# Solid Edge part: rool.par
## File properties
Author: Romil
Template: iso part.par
Last saved by: Romil
Revision: 40
Application: Solid Edge
Accuracy: 0.990
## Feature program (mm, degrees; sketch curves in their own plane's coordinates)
sketch for "unnamed Protrusion 1" plane through (0, 0, 0) normal (1, 0, 0) x-axis (0, 1, 0)
  circle centre (0, 0) radius 11.9
extrude "unnamed Protrusion 1" add finite 3.8 symmetric
sketch for "unnamed Cutout 1" plane through (0, 0, 0) normal (1, 0, 0) x-axis (0, 1, 0)
  arc centre (0, 0) radius 2.55 from (-0.9006, 2.3857) to (1.6939, 1.9061) cw
  line (1.0607, 1.2728) -> (1.6939, 1.9061)
  arc centre (1.1667, 1.1667) radius 0.15 from (1.2728, 1.0607) to (1.0607, 1.2728) cw
  line (1.9061, 1.6939) -> (1.2728, 1.0607)
  arc centre (0, 0) radius 2.55 from (1.9061, 1.6939) to (2.3857, -0.9006) cw
  line (1.8031, -0.9006) -> (2.3857, -0.9006)
  arc centre (1.8031, -1.8031) radius 0.9025 from (0.9006, -1.8031) to (1.8031, -0.9006) cw
  line (0.9006, -2.3857) -> (0.9006, -1.8031)
  arc centre (0, 0) radius 2.55 from (0.9006, -2.3857) to (-1.6939, -1.9061) cw
  line (-1.0607, -1.2728) -> (-1.6939, -1.9061)
  arc centre (-1.1667, -1.1667) radius 0.15 from (-1.2728, -1.0607) to (-1.0607, -1.2728) cw
  line (-1.9061, -1.6939) -> (-1.2728, -1.0607)
  arc centre (0, 0) radius 2.55 from (-1.9061, -1.6939) to (-2.3857, 0.9006) cw
  line (-1.8031, 0.9006) -> (-2.3857, 0.9006)
  arc centre (-1.8031, 1.8031) radius 0.9025 from (-0.9006, 1.8031) to (-1.8031, 0.9006) cw
  line (-0.9006, 2.3857) -> (-0.9006, 1.8031)
extrude "unnamed Cutout 1" cut finite 136.9727 symmetric
sketch for "unnamed Cutout 2" plane through (0, 0, 0) normal (1, 0, 0) x-axis (0, 1, 0)
  circle centre (-8, 0) radius 2.4
extrude "unnamed Cutout 2" cut finite 82.9182 symmetric
sketch for "ExtrudedCutout_44" plane through (-1.9, 0, 0) normal (-1, 0, 0) x-axis (0, -1, 0)
  circle centre (8, 0) radius 3.1
extrude "ExtrudedCutout_44" cut finite 0.9 along -normal
pattern "unnamed Pattern 1" of "unnamed Cutout 2", "ExtrudedCutout_44"
extrude "unnamed Cutout 3" cut finite 82.9182 symmetric
extrude "unnamed Cutout 4" cut finite 0.9
extrude "unnamed Cutout 5" cut finite 82.9182 symmetric
extrude "unnamed Cutout 6" cut finite 0.9
extrude "unnamed Cutout 7" cut finite 82.9182 symmetric
extrude "unnamed Cutout 8" cut finite 0.9
extrude "unnamed Cutout 9" cut finite 82.9182 symmetric
extrude "unnamed Cutout 10" cut finite 0.9
extrude "unnamed Cutout 11" cut finite 82.9182 symmetric
extrude "unnamed Cutout 12" cut finite 0.9
mirror "unnamed Mirror 1" of "ExtrudedCutout_44", "unnamed Pattern 1" about plane through (0, 0, 0) normal (1, 0, 0)
extrude "unnamed Cutout 13" cut finite 0.9
extrude "unnamed Cutout 14" cut finite 82.9182 symmetric
extrude "unnamed Cutout 15" cut finite 0.9
extrude "unnamed Cutout 16" cut finite 82.9182 symmetric
extrude "unnamed Cutout 17" cut finite 0.9
extrude "unnamed Cutout 18" cut finite 82.9182 symmetric
extrude "unnamed Cutout 19" cut finite 0.9
extrude "unnamed Cutout 20" cut finite 82.9182 symmetric
extrude "unnamed Cutout 21" cut finite 0.9
extrude "unnamed Cutout 22" cut finite 82.9182 symmetric
extrude "unnamed Cutout 23" cut finite 0.9
sketch for "unnamed RevolvedCutout 1" plane through (0, 0, 0) normal (0, -1, 0) x-axis (1, 0, 0)
  line (-1.9, 12.9479) -> (1.9, 12.9479)
  line (1.9, 12.9479) -> (1.9, 11.9)
  line (1.9, 11.9) -> (0.835, 11.9)
  arc centre (0.835, 11.7) radius 0.2 from (0.635, 11.7) to (0.835, 11.9) cw
  line (0.635, 11.35) -> (0.635, 11.7)
  arc centre (0.335, 11.35) radius 0.3 from (0.335, 11.05) to (0.635, 11.35) ccw
  line (0.335, 11.05) -> (-0.335, 11.05)
  arc centre (-0.335, 11.35) radius 0.3 from (-0.335, 11.05) to (-0.635, 11.35) cw
  line (-0.635, 11.35) -> (-0.635, 11.7)
  arc centre (-0.835, 11.7) radius 0.2 from (-0.835, 11.9) to (-0.635, 11.7) cw
  line (-0.835, 11.9) -> (-1.9, 11.9)
  line (-1.9, 11.9) -> (-1.9, 12.9479)
revolve "unnamed RevolvedCutout 1" cut finite 360 deg
sketch for "unnamed RevolvedCutout 2" plane through (0, 0, 0) normal (0, -1, 0) x-axis (1, 0, 0)
  line (-6.9503, 0) -> (-6.9503, 8)
  line (-6.9503, 8) -> (-6.9503, 9.55)
  line (-7.0128, 10.2946) -> (-6.9503, 9.55)
  line (-1.9, 10.2946) -> (-7.0128, 10.2946)
  line (-1.9, 9.653) -> (-1.9, 10.2946)
  arc centre (-1.6, 9.653) radius 0.3 from (-1.8368, 9.4687) to (-1.9, 9.653) cw
  line (-1.8368, 9.4687) -> (-1.0632, 8.4744)
  arc centre (-1.3, 8.2902) radius 0.3 from (-1, 8.2902) to (-1.0632, 8.4744) ccw
  line (-1, 3.6) -> (-1, 8.2902)
  line (-1.9, 3.6) -> (-1, 3.6)
  line (-1.9, 0) -> (-1.9, 3.6)
  line (-4.2059, 0) -> (-1.9, 0)
  line (-4.2059, 0) -> (-6.9503, 0)
revolve "unnamed RevolvedCutout 2" cut finite 360 deg
mirror "unnamed Mirror 2" of "unnamed RevolvedCutout 2" about plane through (0, 0, 0) normal (1, 0, 0)
revolve "unnamed RevolvedCutout 3" cut finite 360 deg
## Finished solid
Body 1: solid body, 87 faces, 218 edges, 128 vertices.
  Faces by surface: cylinder 31, torus 28, plane 16, cone 12
  Edges by curve: circle 114, intersection 72, line 32
Bounding box of the edges (mm; curved faces can reach further): 3.800 x 23.800 x 23.800, from (-1.9, -11.9, -11.9) to (1.9, 11.9, 11.9).
Cylindrical faces by radius (mm): R0.15 x2, R0.9025 x2, R2.4 x6, R2.55 x4, R3.1 x12, R3.6 x2, R11.05 x1, R11.9 x2
Conical faces (half-angle, radius in mm at the cone's reference point): 52.1184 deg R8.4744 x6, 52.1184 deg R9.4687 x6
Toroidal faces (ring radius, tube radius in mm): R8.2902 r0.3 x12, R9.653 r0.3 x12, R11.35 r0.3 x2, R11.7 r0.2 x2
Planar faces by outward normal: +x 4, +y 1, +z 1, -x 4, -y 1, -z 1, oblique 4
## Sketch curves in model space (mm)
line (-1.9, 0, 0) -> (-1.9, 0, 3.6)
line (-1.9, 0, 3.6) -> (-1, 0, 3.6)
line (-1, 0, 3.6) -> (-1, 0, 8.2902)
arc centre (-1.3, 0, 8.2902) radius 0.3 from (-1, 0, 8.2902) through (-1.0162, 0, 8.3876) to (-1.0632, 0, 8.4744)
line (-1.8368, 0, 9.4687) -> (-1.0632, 0, 8.4744)
arc centre (-1.6, 0, 9.653) radius 0.3 from (-1.8368, 0, 9.4687) through (-1.8838, 0, 9.5556) to (-1.9, 0, 9.653)
line (-1.9, 0, 9.653) -> (-1.9, 0, 10.2946)
line (-1.9, 0, 10.2946) -> (-7.0128, 0, 10.2946)
line (-7.0128, 0, 10.2946) -> (-6.9503, 0, 9.55)
line (-6.9503, 0, 8) -> (-6.9503, 0, 9.55)
line (-6.9503, 0, 0) -> (-6.9503, 0, 8)
line (-4.2059, 0, 0) -> (-6.9503, 0, 0)
line (-4.2059, 0, 0) -> (-1.9, 0, 0)
circle centre (-1.9, -8, 0) radius 3.1
line (-2.4774, 0, 0) -> (5.0483, 0, 0)
arc centre (-0.335, 0, 3.05) radius 0.3 from (-0.335, 0, 2.75) through (-0.5532, 0, 2.8441) to (-0.635, 0, 3.05)
line (-0.635, 0, 3.05) -> (-0.635, 0, 3.4)
arc centre (-0.835, 0, 3.4) radius 0.2 from (-0.835, 0, 3.6) through (-0.6895, 0, 3.5372) to (-0.635, 0, 3.4)
line (-0.835, 0, 3.6) -> (-1.9, 0, 3.6)
line (-1.9, 0, 3.6) -> (-1.9, 0, 4.6479)
line (-1.9, 0, 4.6479) -> (1.9, 0, 4.6479)
line (1.9, 0, 4.6479) -> (1.9, 0, 3.6)
line (1.9, 0, 3.6) -> (0.835, 0, 3.6)
arc centre (0.835, 0, 3.4) radius 0.2 from (0.635, 0, 3.4) through (0.6978, 0, 3.5455) to (0.835, 0, 3.6)
line (0.635, 0, 3.05) -> (0.635, 0, 3.4)
arc centre (0.335, 0, 3.05) radius 0.3 from (0.335, 0, 2.75) through (0.5532, 0, 2.8441) to (0.635, 0, 3.05)
line (0.335, 0, 2.75) -> (-0.335, 0, 2.75)
arc centre (-0.335, 0, 11.35) radius 0.3 from (-0.335, 0, 11.05) through (-0.5532, 0, 11.1441) to (-0.635, 0, 11.35)
line (-0.635, 0, 11.35) -> (-0.635, 0, 11.7)
arc centre (-0.835, 0, 11.7) radius 0.2 from (-0.835, 0, 11.9) through (-0.6895, 0, 11.8372) to (-0.635, 0, 11.7)
line (-0.835, 0, 11.9) -> (-1.9, 0, 11.9)
line (-1.9, 0, 11.9) -> (-1.9, 0, 12.9479)
line (-1.9, 0, 12.9479) -> (1.9, 0, 12.9479)
line (1.9, 0, 12.9479) -> (1.9, 0, 11.9)
line (1.9, 0, 11.9) -> (0.835, 0, 11.9)
arc centre (0.835, 0, 11.7) radius 0.2 from (0.635, 0, 11.7) through (0.6978, 0, 11.8455) to (0.835, 0, 11.9)
line (0.635, 0, 11.35) -> (0.635, 0, 11.7)
arc centre (0.335, 0, 11.35) radius 0.3 from (0.335, 0, 11.05) through (0.5532, 0, 11.1441) to (0.635, 0, 11.35)
line (0.335, 0, 11.05) -> (-0.335, 0, 11.05)
circle centre (0, -8, 0) radius 2.4
circle centre (0, 0, 0) radius 11.9
circle centre (0, 0, 0) radius 3.6
arc centre (0, 0, 0) radius 2.55 from (0, -2.5456, 0.15) through (0, -2.494, 0.5314) to (0, -2.3857, 0.9006)
line (0, -1.8031, 0.9006) -> (0, -2.3857, 0.9006)
arc centre (0, 0, 0) radius 2.55 from (0, -1.9061, -1.6939) through (0, -2.5075, -0.4635) to (0, -2.3857, 0.9006)
line (0, -1.9061, -1.6939) -> (0, -1.2728, -1.0607)
arc centre (0, -1.1667, -1.1667) radius 0.15 from (0, -1.2728, -1.0607) through (0, -1.0576, -1.0638) to (0, -1.0607, -1.2728)
line (0, -1.0607, -1.2728) -> (0, -1.6939, -1.9061)
arc centre (0, 0, 0) radius 2.55 from (0, 0.9006, -2.3857) through (0, -0.4635, -2.5075) to (0, -1.6939, -1.9061)
line (0, 0.9006, -2.3857) -> (0, 0.9006, -1.8031)
arc centre (0, 1.8031, -1.8031) radius 0.9025 from (0, 0.9006, -1.8031) through (0, 1.1838, -1.1467) to (0, 1.8031, -0.9006)
line (0, 1.8031, -0.9006) -> (0, 2.3857, -0.9006)
arc centre (0, 0, 0) radius 2.55 from (0, 1.9061, 1.6939) through (0, 2.5075, 0.4635) to (0, 2.3857, -0.9006)
line (0, 1.9061, 1.6939) -> (0, 1.2728, 1.0607)
arc centre (0, 1.1667, 1.1667) radius 0.15 from (0, 1.2728, 1.0607) through (0, 1.0576, 1.0638) to (0, 1.0607, 1.2728)
line (0, 1.0607, 1.2728) -> (0, 1.6939, 1.9061)
arc centre (0, 0, 0) radius 2.55 from (0, -0.9006, 2.3857) through (0, 0.4635, 2.5075) to (0, 1.6939, 1.9061)
line (0, -0.9006, 2.3857) -> (0, -0.9006, 1.8031)
arc centre (0, -1.8031, 1.8031) radius 0.9025 from (0, -0.9006, 1.8031) through (0, -1.1838, 1.1467) to (0, -1.8031, 0.9006)
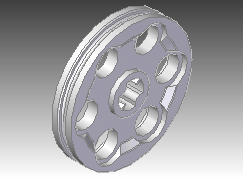
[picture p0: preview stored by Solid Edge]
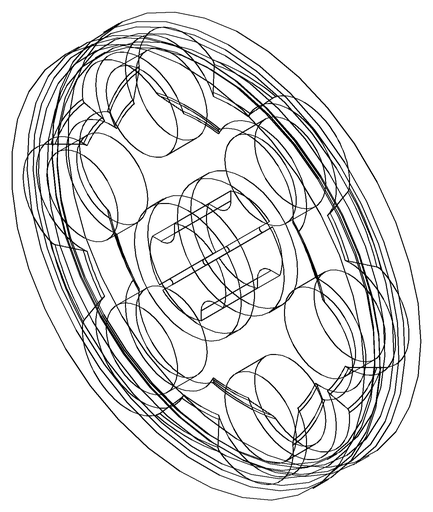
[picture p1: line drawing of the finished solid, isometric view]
